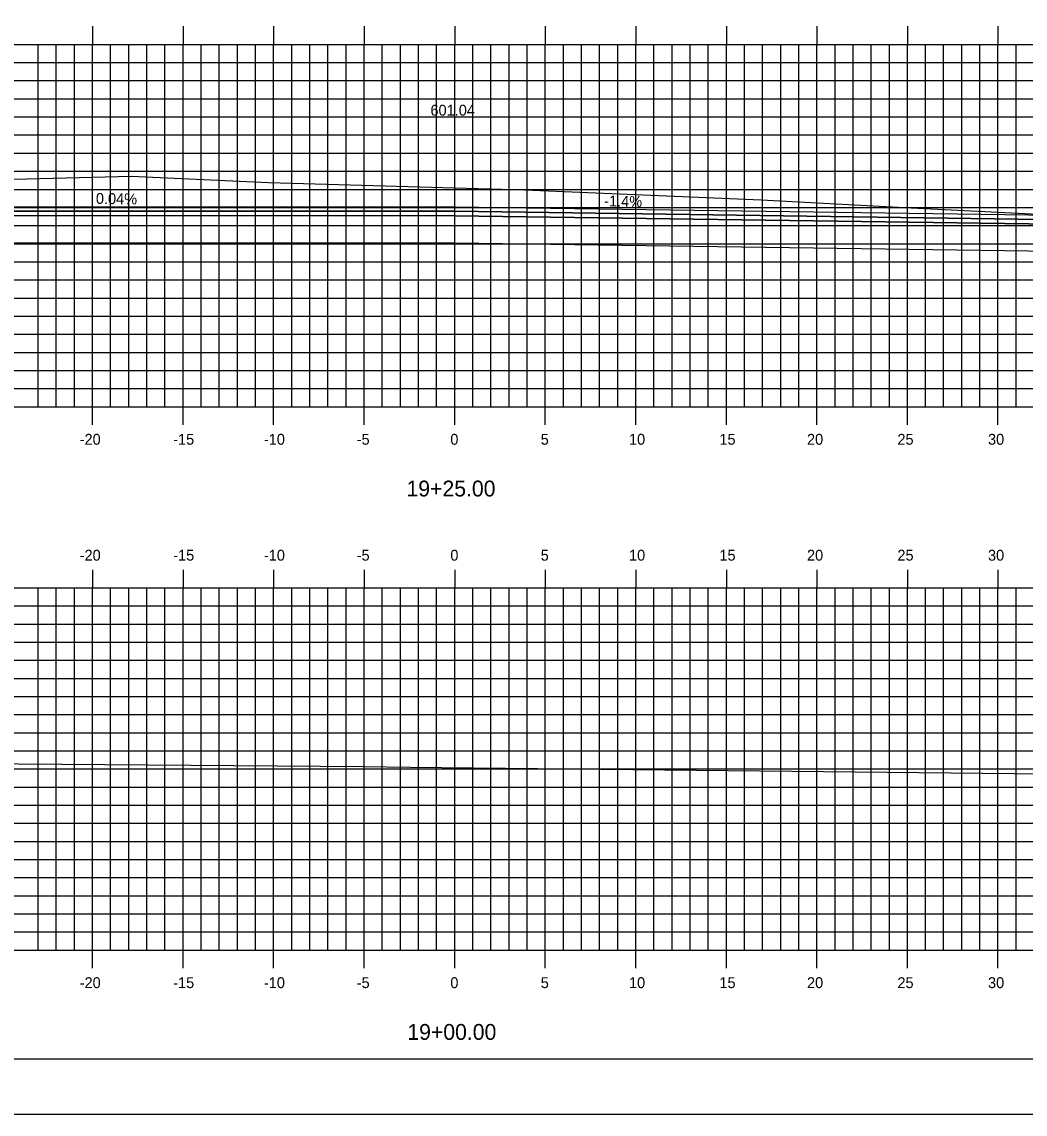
# Model space of a CAD drawing. Extents: x 1048141 to 1048311, y 780904 to 781014.
# Drawn here: x 1048199.8 to 1048255.2, y 780904.1 to 780964.4 of the extents above; entities that cross this region are included whole.
import ezdxf

# ---------------------------------------------------------------- set-up
doc = ezdxf.new("R2010")
doc.units = 0
for name, color, linetype in [('ANNOTATION', 7, 'Continuous'), ('D_Roadway_Centerline', 7, 'Continuous'), ('D_Roadway_Centerline_Text', 7, 'Continuous'), ('D_Roadway_Edge_Pavement', 7, 'Continuous'), ('D_Roadway_Pavement', 7, 'Continuous'), ('D_Roadway_SubGrade', 7, 'Continuous'), ('Default', 7, 'Continuous'), ('H_V ANNOTATION', 7, 'Continuous'), ('MAJOR', 7, 'Continuous'), ('MINOR', 7, 'Continuous'), ('S_Roadway_Centerline', 7, 'Continuous')]:
    doc.layers.add(name, color=color, linetype=linetype)

msp = doc.modelspace()

# ---------------------------------------------------------------- linework, layer by layer
at = {"layer": 'D_Roadway_Centerline'}
msp.add_lwpolyline([(1048169.913, 780954.819), (1048183.644, 780954.167), (1048223.713, 780954.151), (1048293.713, 780953.171)], dxfattribs=at)
at = {"layer": 'D_Roadway_Edge_Pavement'}
msp.add_lwpolyline([(1048183.644, 780953.917), (1048183.644, 780954.167), (1048223.713, 780954.151), (1048293.713, 780953.171), (1048293.709, 780952.921), (1048223.713, 780953.901)], close=True, dxfattribs=at)
at = {"layer": 'D_Roadway_Pavement'}
msp.add_lwpolyline([(1048183.644, 780953.667), (1048183.644, 780953.917), (1048223.713, 780953.901), (1048293.709, 780952.921), (1048293.706, 780952.671), (1048223.713, 780953.651)], close=True, dxfattribs=at)
at = {"layer": 'D_Roadway_SubGrade'}
msp.add_lwpolyline([(1048183.644, 780952.167), (1048183.644, 780953.667), (1048223.713, 780953.651), (1048293.706, 780952.671), (1048293.685, 780951.171), (1048223.713, 780952.151)], close=True, dxfattribs=at)
at = {"layer": 'Default'}
for p, q in [((1048223.712, 780952.151), (1048183.643, 780952.167)), ((1048148.713, 780907.114), (1048308.713, 780907.114))]:
    msp.add_line(p, q, dxfattribs=at)
msp.add_lwpolyline([(1048140.62, 780904.055), (1048310.62, 780904.055), (1048310.62, 781014.055), (1048140.62, 781014.055)], close=True, dxfattribs=at)
at = {"layer": 'MAJOR'}
for p, q in [((1048203.713, 780964.116), (1048203.713, 780963.114)), ((1048208.713, 780964.116), (1048208.713, 780963.114)), ((1048213.713, 780964.116), (1048213.713, 780963.114)), ((1048218.713, 780964.116), (1048218.713, 780963.114)), ((1048223.713, 780964.116), (1048223.713, 780963.114)), ((1048228.713, 780964.116), (1048228.713, 780963.114)), ((1048233.713, 780964.116), (1048233.713, 780963.114)), ((1048238.713, 780964.116), (1048238.713, 780963.114)), ((1048243.713, 780964.116), (1048243.713, 780963.114)), ((1048248.713, 780964.116), (1048248.713, 780963.114)), ((1048253.713, 780964.116), (1048253.713, 780963.114)), ((1048153.713, 780963.114), (1048293.713, 780963.114)), ((1048153.713, 780963.114), (1048293.713, 780963.114)), ((1048203.713, 780943.114), (1048203.713, 780963.114)), ((1048208.713, 780943.114), (1048208.713, 780963.114)), ((1048213.713, 780943.114), (1048213.713, 780963.114)), ((1048218.713, 780943.114), (1048218.713, 780963.114)), ((1048223.713, 780943.114), (1048223.713, 780963.114)), ((1048228.713, 780943.114), (1048228.713, 780963.114)), ((1048233.713, 780943.114), (1048233.713, 780963.114)), ((1048238.713, 780943.114), (1048238.713, 780963.114)), ((1048243.713, 780943.114), (1048243.713, 780963.114)), ((1048248.713, 780943.114), (1048248.713, 780963.114)), ((1048253.713, 780943.114), (1048253.713, 780963.114)), ((1048153.713, 780958.114), (1048293.713, 780958.114)), ((1048153.713, 780953.114), (1048293.713, 780953.114)), ((1048153.713, 780948.114), (1048293.713, 780948.114)), ((1048153.713, 780943.114), (1048293.713, 780943.114)), ((1048153.713, 780943.114), (1048293.713, 780943.114)), ((1048203.713, 780942.112), (1048203.713, 780943.114)), ((1048208.713, 780942.112), (1048208.713, 780943.114)), ((1048213.713, 780942.112), (1048213.713, 780943.114)), ((1048218.713, 780942.112), (1048218.713, 780943.114)), ((1048223.713, 780942.112), (1048223.713, 780943.114)), ((1048228.713, 780942.112), (1048228.713, 780943.114)), ((1048233.713, 780942.112), (1048233.713, 780943.114)), ((1048238.713, 780942.112), (1048238.713, 780943.114)), ((1048243.713, 780942.112), (1048243.713, 780943.114)), ((1048248.713, 780942.112), (1048248.713, 780943.114)), ((1048253.713, 780942.112), (1048253.713, 780943.114)), ((1048203.713, 780934.116), (1048203.713, 780933.114)), ((1048208.713, 780934.116), (1048208.713, 780933.114)), ((1048213.713, 780934.116), (1048213.713, 780933.114)), ((1048218.713, 780934.116), (1048218.713, 780933.114)), ((1048223.713, 780934.116), (1048223.713, 780933.114)), ((1048228.713, 780934.116), (1048228.713, 780933.114)), ((1048233.713, 780934.116), (1048233.713, 780933.114)), ((1048238.713, 780934.116), (1048238.713, 780933.114)), ((1048243.713, 780934.116), (1048243.713, 780933.114)), ((1048248.713, 780934.116), (1048248.713, 780933.114)), ((1048253.713, 780934.116), (1048253.713, 780933.114)), ((1048153.713, 780933.114), (1048293.713, 780933.114)), ((1048153.713, 780933.114), (1048293.713, 780933.114)), ((1048203.713, 780913.114), (1048203.713, 780933.114)), ((1048208.713, 780913.114), (1048208.713, 780933.114)), ((1048213.713, 780913.114), (1048213.713, 780933.114)), ((1048218.713, 780913.114), (1048218.713, 780933.114)), ((1048223.713, 780913.114), (1048223.713, 780933.114)), ((1048228.713, 780913.114), (1048228.713, 780933.114)), ((1048233.713, 780913.114), (1048233.713, 780933.114)), ((1048238.713, 780913.114), (1048238.713, 780933.114)), ((1048243.713, 780913.114), (1048243.713, 780933.114)), ((1048248.713, 780913.114), (1048248.713, 780933.114)), ((1048253.713, 780913.114), (1048253.713, 780933.114)), ((1048153.713, 780928.114), (1048293.713, 780928.114)), ((1048153.713, 780923.114), (1048293.713, 780923.114)), ((1048153.713, 780918.114), (1048293.713, 780918.114)), ((1048153.713, 780913.114), (1048293.713, 780913.114)), ((1048153.713, 780913.114), (1048293.713, 780913.114)), ((1048203.713, 780912.112), (1048203.713, 780913.114)), ((1048208.713, 780912.112), (1048208.713, 780913.114)), ((1048213.713, 780912.112), (1048213.713, 780913.114)), ((1048218.713, 780912.112), (1048218.713, 780913.114)), ((1048223.713, 780912.112), (1048223.713, 780913.114)), ((1048228.713, 780912.112), (1048228.713, 780913.114)), ((1048233.713, 780912.112), (1048233.713, 780913.114)), ((1048238.713, 780912.112), (1048238.713, 780913.114)), ((1048243.713, 780912.112), (1048243.713, 780913.114)), ((1048248.713, 780912.112), (1048248.713, 780913.114)), ((1048253.713, 780912.112), (1048253.713, 780913.114))]:
    msp.add_line(p, q, dxfattribs=at)
at = {"layer": 'MINOR'}
for p, q in [((1048200.713, 780943.114), (1048200.713, 780963.114)), ((1048201.713, 780943.114), (1048201.713, 780963.114)), ((1048202.713, 780943.114), (1048202.713, 780963.114)), ((1048204.713, 780943.114), (1048204.713, 780963.114)), ((1048205.713, 780943.114), (1048205.713, 780963.114)), ((1048206.713, 780943.114), (1048206.713, 780963.114)), ((1048207.713, 780943.114), (1048207.713, 780963.114)), ((1048209.713, 780943.114), (1048209.713, 780963.114)), ((1048210.713, 780943.114), (1048210.713, 780963.114)), ((1048211.713, 780943.114), (1048211.713, 780963.114)), ((1048212.713, 780943.114), (1048212.713, 780963.114)), ((1048214.713, 780943.114), (1048214.713, 780963.114)), ((1048215.713, 780943.114), (1048215.713, 780963.114)), ((1048216.713, 780943.114), (1048216.713, 780963.114)), ((1048217.713, 780943.114), (1048217.713, 780963.114)), ((1048219.713, 780943.114), (1048219.713, 780963.114)), ((1048220.713, 780943.114), (1048220.713, 780963.114)), ((1048221.713, 780943.114), (1048221.713, 780963.114)), ((1048222.713, 780943.114), (1048222.713, 780963.114)), ((1048224.713, 780943.114), (1048224.713, 780963.114)), ((1048225.713, 780943.114), (1048225.713, 780963.114)), ((1048226.713, 780943.114), (1048226.713, 780963.114)), ((1048227.713, 780943.114), (1048227.713, 780963.114)), ((1048229.713, 780943.114), (1048229.713, 780963.114)), ((1048230.713, 780943.114), (1048230.713, 780963.114)), ((1048231.713, 780943.114), (1048231.713, 780963.114)), ((1048232.713, 780943.114), (1048232.713, 780963.114)), ((1048234.713, 780943.114), (1048234.713, 780963.114)), ((1048235.713, 780943.114), (1048235.713, 780963.114)), ((1048236.713, 780943.114), (1048236.713, 780963.114)), ((1048237.713, 780943.114), (1048237.713, 780963.114)), ((1048239.713, 780943.114), (1048239.713, 780963.114)), ((1048240.713, 780943.114), (1048240.713, 780963.114)), ((1048241.713, 780943.114), (1048241.713, 780963.114)), ((1048242.713, 780943.114), (1048242.713, 780963.114)), ((1048244.713, 780943.114), (1048244.713, 780963.114)), ((1048245.713, 780943.114), (1048245.713, 780963.114)), ((1048246.713, 780943.114), (1048246.713, 780963.114)), ((1048247.713, 780943.114), (1048247.713, 780963.114)), ((1048249.713, 780943.114), (1048249.713, 780963.114)), ((1048250.713, 780943.114), (1048250.713, 780963.114)), ((1048251.713, 780943.114), (1048251.713, 780963.114)), ((1048252.713, 780943.114), (1048252.713, 780963.114)), ((1048254.713, 780943.114), (1048254.713, 780963.114)), ((1048153.713, 780962.114), (1048293.713, 780962.114)), ((1048153.713, 780961.114), (1048293.713, 780961.114)), ((1048153.713, 780960.114), (1048293.713, 780960.114)), ((1048153.713, 780959.114), (1048293.713, 780959.114)), ((1048153.713, 780957.114), (1048293.713, 780957.114)), ((1048153.713, 780956.114), (1048293.713, 780956.114)), ((1048153.713, 780955.114), (1048293.713, 780955.114)), ((1048153.713, 780954.114), (1048293.713, 780954.114)), ((1048153.713, 780952.114), (1048293.713, 780952.114)), ((1048153.713, 780951.114), (1048293.713, 780951.114)), ((1048153.713, 780950.114), (1048293.713, 780950.114)), ((1048153.713, 780949.114), (1048293.713, 780949.114)), ((1048153.713, 780947.114), (1048293.713, 780947.114)), ((1048153.713, 780946.114), (1048293.713, 780946.114)), ((1048153.713, 780945.114), (1048293.713, 780945.114)), ((1048153.713, 780944.114), (1048293.713, 780944.114)), ((1048200.713, 780913.114), (1048200.713, 780933.114)), ((1048201.713, 780913.114), (1048201.713, 780933.114)), ((1048202.713, 780913.114), (1048202.713, 780933.114)), ((1048204.713, 780913.114), (1048204.713, 780933.114)), ((1048205.713, 780913.114), (1048205.713, 780933.114)), ((1048206.713, 780913.114), (1048206.713, 780933.114)), ((1048207.713, 780913.114), (1048207.713, 780933.114)), ((1048209.713, 780913.114), (1048209.713, 780933.114)), ((1048210.713, 780913.114), (1048210.713, 780933.114)), ((1048211.713, 780913.114), (1048211.713, 780933.114)), ((1048212.713, 780913.114), (1048212.713, 780933.114)), ((1048214.713, 780913.114), (1048214.713, 780933.114)), ((1048215.713, 780913.114), (1048215.713, 780933.114)), ((1048216.713, 780913.114), (1048216.713, 780933.114)), ((1048217.713, 780913.114), (1048217.713, 780933.114)), ((1048219.713, 780913.114), (1048219.713, 780933.114)), ((1048220.713, 780913.114), (1048220.713, 780933.114)), ((1048221.713, 780913.114), (1048221.713, 780933.114)), ((1048222.713, 780913.114), (1048222.713, 780933.114)), ((1048224.713, 780913.114), (1048224.713, 780933.114)), ((1048225.713, 780913.114), (1048225.713, 780933.114)), ((1048226.713, 780913.114), (1048226.713, 780933.114)), ((1048227.713, 780913.114), (1048227.713, 780933.114)), ((1048229.713, 780913.114), (1048229.713, 780933.114)), ((1048230.713, 780913.114), (1048230.713, 780933.114)), ((1048231.713, 780913.114), (1048231.713, 780933.114)), ((1048232.713, 780913.114), (1048232.713, 780933.114)), ((1048234.713, 780913.114), (1048234.713, 780933.114)), ((1048235.713, 780913.114), (1048235.713, 780933.114)), ((1048236.713, 780913.114), (1048236.713, 780933.114)), ((1048237.713, 780913.114), (1048237.713, 780933.114)), ((1048239.713, 780913.114), (1048239.713, 780933.114)), ((1048240.713, 780913.114), (1048240.713, 780933.114)), ((1048241.713, 780913.114), (1048241.713, 780933.114)), ((1048242.713, 780913.114), (1048242.713, 780933.114)), ((1048244.713, 780913.114), (1048244.713, 780933.114)), ((1048245.713, 780913.114), (1048245.713, 780933.114)), ((1048246.713, 780913.114), (1048246.713, 780933.114)), ((1048247.713, 780913.114), (1048247.713, 780933.114)), ((1048249.713, 780913.114), (1048249.713, 780933.114)), ((1048250.713, 780913.114), (1048250.713, 780933.114)), ((1048251.713, 780913.114), (1048251.713, 780933.114)), ((1048252.713, 780913.114), (1048252.713, 780933.114)), ((1048254.713, 780913.114), (1048254.713, 780933.114)), ((1048153.713, 780932.114), (1048293.713, 780932.114)), ((1048153.713, 780931.114), (1048293.713, 780931.114)), ((1048153.713, 780930.114), (1048293.713, 780930.114)), ((1048153.713, 780929.114), (1048293.713, 780929.114)), ((1048153.713, 780927.114), (1048293.713, 780927.114)), ((1048153.713, 780926.114), (1048293.713, 780926.114)), ((1048153.713, 780925.114), (1048293.713, 780925.114)), ((1048153.713, 780924.114), (1048293.713, 780924.114)), ((1048153.713, 780922.114), (1048293.713, 780922.114)), ((1048153.713, 780921.114), (1048293.713, 780921.114)), ((1048153.713, 780920.114), (1048293.713, 780920.114)), ((1048153.713, 780919.114), (1048293.713, 780919.114)), ((1048153.713, 780917.114), (1048293.713, 780917.114)), ((1048153.713, 780916.114), (1048293.713, 780916.114)), ((1048153.713, 780915.114), (1048293.713, 780915.114)), ((1048153.713, 780914.114), (1048293.713, 780914.114))]:
    msp.add_line(p, q, dxfattribs=at)
at = {"layer": 'S_Roadway_Centerline'}
for points in [[(1048153.713, 780954.572), (1048159.825, 780954.58), (1048163.027, 780954.664), (1048167.266, 780954.693), (1048169.627, 780954.814), (1048180.042, 780954.995), (1048189.22, 780955.536), (1048196.477, 780955.609), (1048205.851, 780955.838), (1048213.438, 780955.489), (1048227.587, 780955.088), (1048240.634, 780954.526), (1048248.544, 780954.12), (1048264.413, 780953.312), (1048264.419, 780953.312), (1048264.422, 780953.313), (1048264.434, 780953.311), (1048276.919, 780952.999), (1048290.846, 780952.301), (1048293.713, 780952.036)], [(1048153.713, 780923.736), (1048164.413, 780923.663), (1048165.392, 780923.664), (1048166.788, 780923.659), (1048168.702, 780923.63), (1048218.665, 780923.246), (1048221.263, 780923.212), (1048270.425, 780922.704), (1048273.522, 780922.631), (1048273.524, 780922.634), (1048293.713, 780922.409)]]:
    msp.add_lwpolyline(points, dxfattribs=at)

# ---------------------------------------------------------------- texts
at = {"layer": 'ANNOTATION'}
for s, rotation, p in [('0.04%', 359.21367, (1048203.898, 780954.312)), ('-1.4%', 358.85424, (1048231.963, 780954.179))]:
    msp.add_text(s, height=0.6, rotation=rotation, dxfattribs=at).set_placement(p)
at = {"layer": 'D_Roadway_Centerline_Text'}
msp.add_text('601.04', height=0.6, dxfattribs=at).set_placement((1048222.375, 780959.183))
at = {"layer": 'H_V ANNOTATION'}
for s, height, p in [('-20', 0.6, (1048203.006, 780941.014)), ('-15', 0.6, (1048208.17, 780941.014)), ('-10', 0.6, (1048213.178, 780941.014)), ('-5', 0.6, (1048218.303, 780941.014)), ('0', 0.6, (1048223.472, 780941.014)), ('5', 0.6, (1048228.464, 780941.014)), ('10', 0.6, (1048233.338, 780941.014)), ('15', 0.6, (1048238.33, 780941.014)), ('20', 0.6, (1048243.167, 780941.014)), ('25', 0.6, (1048248.159, 780941.014)), ('30', 0.6, (1048253.162, 780941.014)), ('19+25.00', 0.875, (1048221.052, 780938.157)), ('-20', 0.6, (1048203.006, 780934.614)), ('-15', 0.6, (1048208.17, 780934.614)), ('-10', 0.6, (1048213.178, 780934.614)), ('-5', 0.6, (1048218.303, 780934.614)), ('0', 0.6, (1048223.472, 780934.614)), ('5', 0.6, (1048228.464, 780934.614)), ('10', 0.6, (1048233.338, 780934.614)), ('15', 0.6, (1048238.33, 780934.614)), ('20', 0.6, (1048243.167, 780934.614)), ('25', 0.6, (1048248.159, 780934.614)), ('30', 0.6, (1048253.162, 780934.614)), ('-20', 0.6, (1048203.006, 780911.014)), ('-15', 0.6, (1048208.17, 780911.014)), ('-10', 0.6, (1048213.178, 780911.014)), ('-5', 0.6, (1048218.303, 780911.014)), ('0', 0.6, (1048223.472, 780911.014)), ('5', 0.6, (1048228.464, 780911.014)), ('10', 0.6, (1048233.338, 780911.014)), ('15', 0.6, (1048238.33, 780911.014)), ('20', 0.6, (1048243.167, 780911.014)), ('25', 0.6, (1048248.159, 780911.014)), ('30', 0.6, (1048253.162, 780911.014)), ('19+00.00', 0.875, (1048221.099, 780908.157))]:
    msp.add_text(s, height=height, dxfattribs=at).set_placement(p)

doc.saveas('drawing.dxf')
